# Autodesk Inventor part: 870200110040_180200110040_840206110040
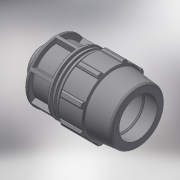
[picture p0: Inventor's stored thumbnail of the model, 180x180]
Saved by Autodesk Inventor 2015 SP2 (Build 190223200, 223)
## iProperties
Created: 2017-02
Part Number: 870200110040_180200110040_840206110040
Material: Generic
Description: PLASSON MALE ADAPTOR 110-4"
Document SubType Name: Modeling
Designer: KIM
Mass: 964.158 g
Surface Area: 1468.9 cm^2
Volume: 964.158 cm^3
Density: 1 g/cm^3
Appearance: Default
Author: KIM
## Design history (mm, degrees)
derived "87020.ipt"
feature "Solid1::87020.ipt"
tag "TaggingFeature1"
body "Solid1"
other parameters: "d4" = 38.14286, "d5" = 66.75, "d7" = 181, "d8" = 135.75, "d9" = 38.14286, "d11" = 7.62857, "d12" = 144.8, "d13" = 120 deg, "d14" = 143, "d15" = 6 deg, "d16" = 162.9, "d18" = 5.5, "d19" = 35 deg, "d20" = 17.5 deg, "d21" = 168.33, "d23" = 0, "d25" = 360 deg, "d27" = 3.62, "d34" = 9.05, "d36" = 0, "d42" = 66.75, "d43" = 5.43, "d46" = 3.3, "d49" = 215, "d51" = 267, "d52" = 42, "d53" = 2.2, "d55" = 360 deg, "d57" = 113.03, "d58" = 79.121, "d59" = 53.4, "d61" = 159.642, "d62" = 4.56857, "d63" = 4.56857, "d66" = 9.13714, "E_" = 181, "H_" = 267, "l_" = 215, "l_2" = 42, "R_" = 113.03, "d60" = 22.84286
